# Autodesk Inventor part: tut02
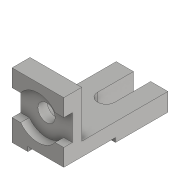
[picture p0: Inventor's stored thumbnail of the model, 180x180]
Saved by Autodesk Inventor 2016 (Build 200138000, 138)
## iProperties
Created: 2015-03
Part Number: tut02
Material: Generic
Document SubType Name: Modeling
Designer: Sandeep
Density: 1 g/cm^3
Appearance: Default
Author: Sandeep
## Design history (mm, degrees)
sketch "Sketch1"
  geometry: L1 (0, 90)-(25, 90); L2 (25, 90)-(25, 25); L3 (25, 25)-(145, 25); L4 (145, 25)-(145, 0); L5 (145, 0)-(0, 0); L6 (0, 0)-(0, 90)
  constraints: 12 end point, 5 perpendicular, 1 horizontal
  dimensions: "d0" = 25 distance of L1.start L1.end; "d1" = 90 distance of L5.end L1.start; "d2" = 145 distance of L4.end L5.end; "d3" = 25 distance of L3.end L4.end
extrude "Extrusion1" new body sketch "Sketch1" stored distance "d4" = 72; taper "d5" = 0 deg
sketch "Sketch2"
  geometry: L1 (0, 0)-(0, 145) reference; L2 (0, 0)-(-6, 0); L3 (-6, 0)-(-6, 72); L4 (-6, 72)-(0, 72); L5 (0, 72)-(0, 0)
  constraints: 8 end point, 2 parallel, 1 horizontal, 1 perpendicular
  dimensions: "d6" = 6 distance between parallel lines of L1 L3; "d7" = 72 distance of L2.end L3.end
extrude "Extrusion2" cut sketch "Sketch2" distance "d8" = 50; taper "d9" = 0 deg
sketch "Sketch3"
  geometry: L1 (12, -24)-(0, -24); L2 (0, -24)-(0, -60); L3 (0, -60)-(12, -60); L4 (36, -42)-(36, -101.863); L5 (60, -24)-(72, -24); L6 (72, -24)-(72, -60); L7 (72, -60)-(60, -60); L8 (72, 0)-(72, -84) reference; L9 (0, -90)-(0, 0) reference; L10 (72, -90)-(22, -90) reference; L11 (36, -42)-(119.122, -42); A1 r 30 centre (36, -42) between (12, -60) and (60, -60); A2 r 30 centre (36, -42) between (60, -24) and (12, -24); 1 further point
  constraints: 16 end point, 5 horizontal, 4 point on circle, 2 centre point, 2 collinear, 2 vertical, 1 perpendicular, 3 other
  dimensions: "d11" = 36 distance from line of L2 L4.start; "d12" = 48 distance from line of L10 L4.start; "d13" = 36 distance of L1.end L2.end; "d14" = 36 distance of L5.end L6.end; "d15" = 30 radius of A2
extrude "Extrusion3" cut sketch "Sketch3" distance "d16" = 12; taper "d17" = 0 deg
sketch "Sketch4"
  geometry: L1 (0, 120)-(72, 120) reference; L2 (24, 120)-(24, 70); L3 (48, 70)-(48, 120); L4 (0, 0)-(0, 120) reference; A1 r 12 centre (36, 70) between (24, 70) and (48, 70); 1 further point
  constraints: 4 end point, 2 point on circle, 2 point on line, 2 tangent, 1 centre point, 1 parallel, 1 vertical
  dimensions: "d18" = 36 distance from line of A1.centre L4; "d19" = 12 radius of A1; "d20" = 50 distance from line of L1 A1.centre
extrude "Extrusion4" cut sketch "Sketch4" stored distance "d21" = 12; taper "d22" = 0 deg
sketch "Sketch5"
  geometry: L1 (72, -24)-(72, -60) reference; C1 r 12 at (36, -42); 1 further point
  constraints: 1 centre point
  dimensions: "d23" = 24 diameter of C1; "d24" = 48 distance of point (36, -90) C1.centre; "d25" = 36 distance from line of L1 C1.centre
extrude "Extrusion5" cut sketch "Sketch5" stored distance "d26" = 12; taper "d27" = 0 deg
body "Solid1"
